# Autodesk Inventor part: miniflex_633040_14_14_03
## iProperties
Shininess: 64.0
Length Units: 11269
Angle Units: 11279
Time Units: 11290
Mass Units: 11283
Length Display Precision: 3
Angle Display Precision: 2
Compacted: True
Part Number: miniflex_633040_14_14_03
Document SubType Name: Modeling
Created: 2005-02
Material: Par défaut
Designer: LEGERET Philippe
Density: 0.0
Volumn: 0.0
Area: 0.0
PropertySet Name: Model Information
Control State: 0
Master: False
Checked Out: False
Author: LEGERET Philippe
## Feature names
1. Base1
